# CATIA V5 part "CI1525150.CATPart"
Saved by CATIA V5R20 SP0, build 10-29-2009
Part number: CI1525150
Bounding box of the stored display mesh (mm): x -24 to 24, y -19.758 to 184.5, z -29.741 to 27.753
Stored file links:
  C:\Users\Raffaele\Desktop\3D X SITO CF\BOLEX\19-INCLINED ASSEMBLY REF_CI\CI1525150.CATPart

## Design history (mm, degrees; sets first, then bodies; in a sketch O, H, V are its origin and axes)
Set1
  DatumSurface1 to DatumSurface16 "MANIFOLD_SOLID_BREP #393"
  DatumSurface17 to DatumSurface39 "MANIFOLD_SOLID_BREP #1138"
Body1 (main body)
